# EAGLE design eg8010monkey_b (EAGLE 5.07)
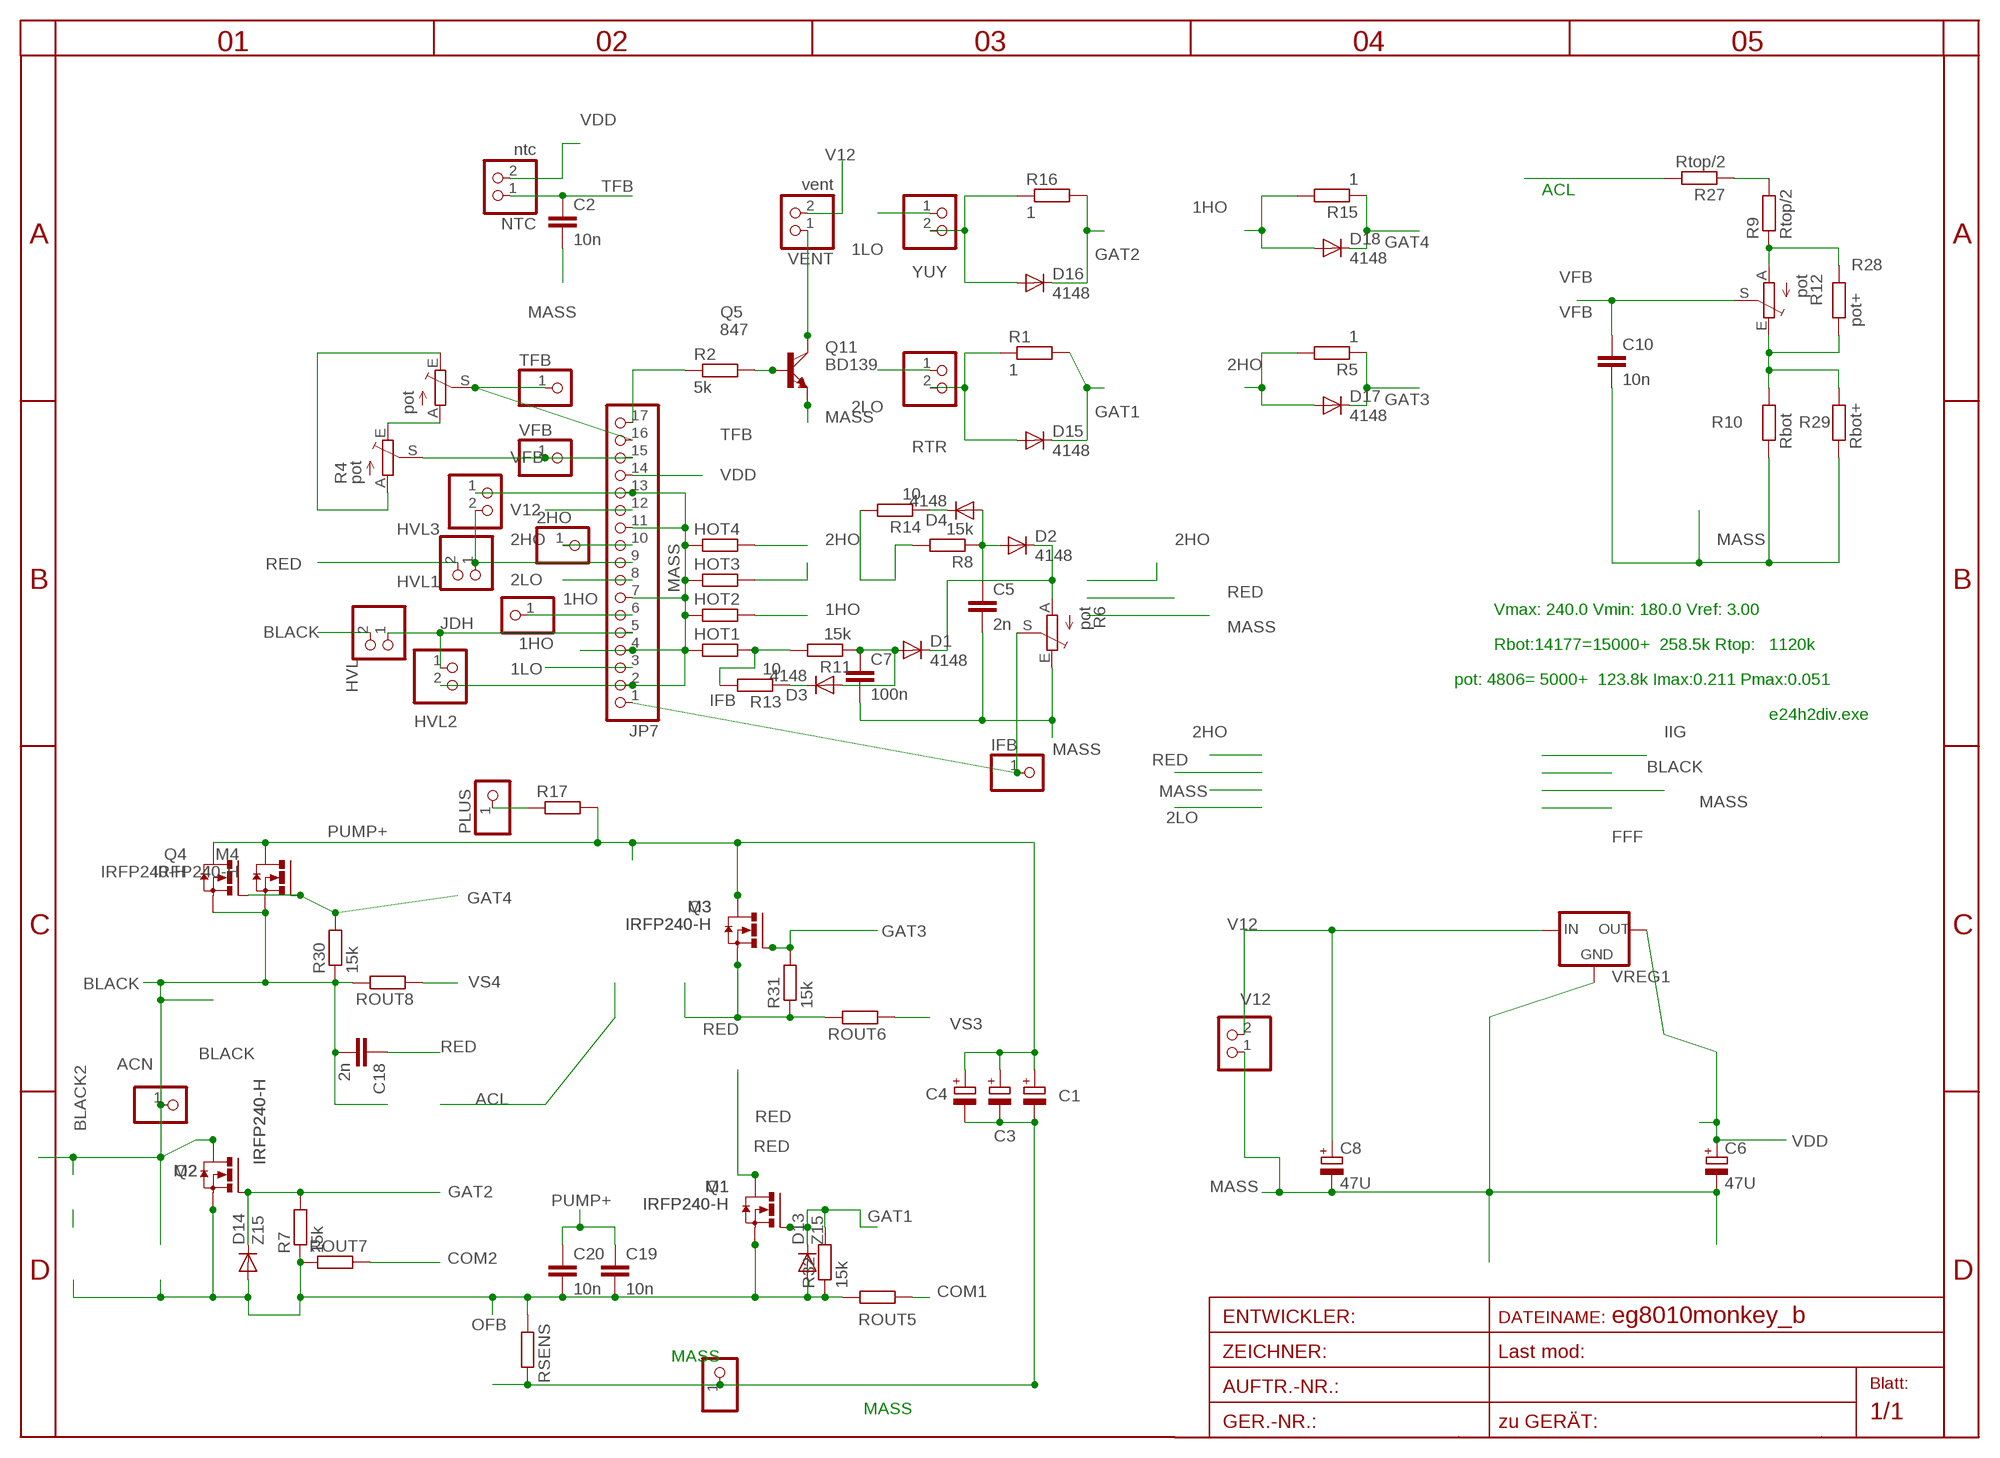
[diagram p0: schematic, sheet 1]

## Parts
1HO  PINHD-1X11MM0  [1X1MM0]
1LO  PINHD-1X2STR  [1X02]
2HO  PINHD-1X11MM0  [1X1MM0]
2LO  PINHD-1X2STR  [1X02]
BLACK2  ACN  PINHD-1X12MM3  [1X2MM3]
C1  CPOL-EUE5-13  [E5-13]
C2  10n  C-EUC0805  [C0805]
C3  CPOL-EUE5-13  [E5-13]
C4  CPOL-EUE5-13  [E5-13]
C5  2n  C-EUC0805  [C0805]
C6  47U  CPOL-EUSMCA  [SMC_A]
C7  100n  C-EUC0805  [C0805]
C8  47U  CPOL-EUSMCA  [SMC_A]
C10  10n  C-EUC0805  [C0805]
C18  2n  C-EU050-024X044  [C050-024X044]
C19  10n  C-EU050-024X044  [C050-024X044]
C20  10n  C-EU050-024X044  [C050-024X044]
D1  4148  DIODE-MINIMELF  [MINIMELF]
D2  4148  DIODE-MINIMELF  [MINIMELF]
D3  4148  DIODE-MINIMELF  [MINIMELF]
D4  4148  DIODE-MINIMELF  [MINIMELF]
D13  Z15  DIODE-MINIMELF  [MINIMELF]
D14  Z15  DIODE-MINIMELF  [MINIMELF]
D15  4148  DIODE-MINIMELF  [MINIMELF]
D16  4148  DIODE-MINIMELF  [MINIMELF]
D17  4148  DIODE-MINIMELF  [MINIMELF]
D18  4148  DIODE-MINIMELF  [MINIMELF]
HOT1  R-EU_R0805  [R0805]
HOT2  R-EU_R0805  [R0805]
HOT3  R-EU_R0805  [R0805]
HOT4  R-EU_R0805  [R0805]
HVL  PINHD-1X2STR  [1X02]
HVL1  PINHD-1X2STR  [1X02]
HVL2  PINHD-1X2STR  [1X02]
HVL3  PINHD-1X2STR  [1X02]
IFB  PINHD-1X11MM0  [1X1MM0]
JP7  PINHD-1X17  [1X17]
M1  IRFP240-H  [TO247BH]
M2  IRFP240-H  [TO247BH]
M3  IRFP240-H  [TO247BH]
M4  IRFP240-H  [TO247BH]
MINUS  PINHD-1X12MM3  [1X2MM3]
NTC  ntc  PINHD-1X2STR  [1X02]
PLUS  PINHD-1X12MM3  [1X2MM3]
Q1  IRFP240-H  [TO247BH]
Q2  IRFP240-H  [TO247BH]
Q3  IRFP240-H  [TO247BH]
Q4  IRFP240-H  [TO247BH]
Q5  847  BC847SMD  [SOT23]
Q11  BD139  [TO126AV]
R1  1  R-EU_R2512  [R2512]
R2  5k  R-EU_R0805  [R0805]
R3  pot  TRIM_EU-RAND160  [RANDL]
R4  pot  TRIM_EU-RAND160  [RANDL]
R5  1  R-EU_R2512  [R2512]
R6  pot  TRIM_EU-RAND160  [RANDL]
R7  15k  R-EU_R1206  [R1206]
R8  15k  R-EU_R0805  [R0805]
R9  Rtop/2  R-EU_R1206  [R1206]
R10  Rbot  R-EU_R0805  [R0805]
R11  15k  R-EU_R0805  [R0805]
R12  pot  TRIM_EU-B64Y  [B64Y]
R13  10  R-EU_R0805  [R0805]
R14  10  R-EU_R0805  [R0805]
R15  1  R-EU_R2512  [R2512]
R16  1  R-EU_R2512  [R2512]
R17  R-EU_0309/10  [0309/10]
R27  Rtop/2  R-EU_R1206  [R1206]
R28  pot+  R-EU_R0805  [R0805]
R29  Rbot+  R-EU_R0805  [R0805]
R30  15k  R-EU_R1206  [R1206]
R31  15k  R-EU_R1206  [R1206]
R32  15k  R-EU_R1206  [R1206]
ROUT5  R-EU_R2512  [R2512]
ROUT6  R-EU_R2512  [R2512]
ROUT7  R-EU_R2512  [R2512]
ROUT8  R-EU_R2512  [R2512]
RSENS  R-EU_WIRE  [WIRE]
TFB  PINHD-1X11MM0  [1X1MM0]
V12  PINHD-1X2STR  [1X02]
VENT  vent  PINHD-1X2STR  [1X02]
VFB  PINHD-1X11MM0  [1X1MM0]
VREG1  LP2950TO92-2MIL  [TO92-2MIL]

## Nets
1HO: 1HO.1 D18.A HOT2.2 JP7.6 R8.2 R14.2 R15.2
1LO: 1LO.1 HOT1.2 JP7.3 R11.2 R13.2
2HO: 2HO.1 D17.A HOT4.2 JP7.10 R5.2
2LO: 2LO.1 HOT3.2 JP7.8
ACL: R27.2
BLACK: BLACK2.1 C18.2 HVL.2 M2.D M4.S Q2.D Q4.S R30.1 ROUT8.2
COM1: ROUT5.1
COM2: ROUT7.2
DFG: HVL1.1 HVL3.2 JP7.9
GAT1: D13.C D15.C M1.G Q1.G R1.2 R32.2
GAT2: D14.C D16.C M2.G Q2.G R7.2 R16.2
GAT3: D17.C M3.G Q3.G R5.1 R31.2
GAT4: D18.C M4.G Q4.G R15.1 R30.2
IFB: IFB.1 JP7.1 R6.S
JDH: HVL2.1 HVL.1 JP7.5
MASS: C1.- C2.2 C3.- C4.- C5.2 C6.- C7.2 C8.- C10.2 HOT1.1 HOT2.1 HOT3.1 HOT4.1 HVL2.2 HVL3.1 JP7.2 JP7.4 JP7.7 JP7.11 JP7.13 MINUS.1 Q5.2(E) Q11.E R3.A R4.E R6.E R10.1 R29.1 RSENS.2 V12.1 VREG1.2(GND)
N$1: Q5.3(C) Q11.C VENT.1
N$2: Q5.1(B) Q11.B R2.2
N$3: JP7.17 R2.1
N$4: D1.C D2.C R6.A
N$5: PLUS.1 R17.1
N$6: C5.1 D2.A D4.A R8.1
N$7: C7.1 D1.A D3.A R11.1
N$8: D3.C R13.1
N$11: D4.C R14.1
N$23: R9.2 R27.1
N$29: R10.2 R12.E R28.1 R29.2
N$30: R9.1 R12.A R28.2
OFB: C19.2 C20.2 D13.A D14.A M1.S M2.S Q1.S Q2.S R7.1 R32.1 ROUT5.2 ROUT7.1 RSENS.1
PUMP+: C1.+ C3.+ C4.+ C19.1 C20.1 M3.D M4.D Q3.D Q4.D R17.2
RED: C18.1 HVL1.2 M1.D M3.S Q1.D Q3.S R31.1 ROUT6.2
RTR: 2LO.2 D15.A R1.1
TFB: C2.1 JP7.16 NTC.1 R3.S TFB.1
V12: C8.+ JP7.12 V12.2 VENT.2 VREG1.3(IN)
VDD: C6.+ JP7.14 NTC.2 R3.E R4.A VREG1.1(OUT)
VFB: C10.1 JP7.15 R4.S R12.S VFB.1
VS3: ROUT6.1
VS4: ROUT8.1
YUY: 1LO.2 D16.A R16.1

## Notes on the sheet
- Vmax: 240.0 Vmin: 180.0 Vref: 3.00
- Rbot:14177=15000+  258.5k Rtop:   1120k
- pot: 4806= 5000+  123.8k Imax:0.211 Pmax:0.051
- e24h2div.exe

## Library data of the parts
1HO 2HO BLACK2 IFB MINUS PLUS TFB VFB = pinhead:PINHD-1X1: PIN HEADER
1LO 2LO HVL HVL1-HVL3 NTC V12 VENT = pinhead:PINHD-1X2: PIN HEADER
C1 C3 C4 C6 C8 = rcl:CPOL-EU: POLARIZED CAPACITOR, European symbol
C2 C5 C7 C10 C18-C20 = rcl:C-EU: CAPACITOR, European symbol
D1-D4 D13-D18 = diode:DIODE-: DIODE
HOT1-HOT4 R1 R2 R5 R7 R8 R11 R13-R17 R30-R32 ROUT5-ROUT8 RSENS = rcl:R-EU_: RESISTOR, European symbol
JP7 = pinhead:PINHD-1X17: PIN HEADER
M1-M4 Q1-Q4 = transistor-power:IRFP240: HEXFET Power MosFet Source: http://www.irf.com/
Q5 = transistor-npn:BC847*: NPN Transistor
Q11 = transistor-power:BD139: NPN TRANSISTOR
R3 R4 R6 R12 = pot:TRIM_EU-: POTENTIOMETER
R9 R10 R27-R29 = rcl-2:R-EU_: RESISTOR, European symbol
VREG1 = v-reg:LP2950?*: Source: http://cache.national.com/ds/LP/LP2950.pdf

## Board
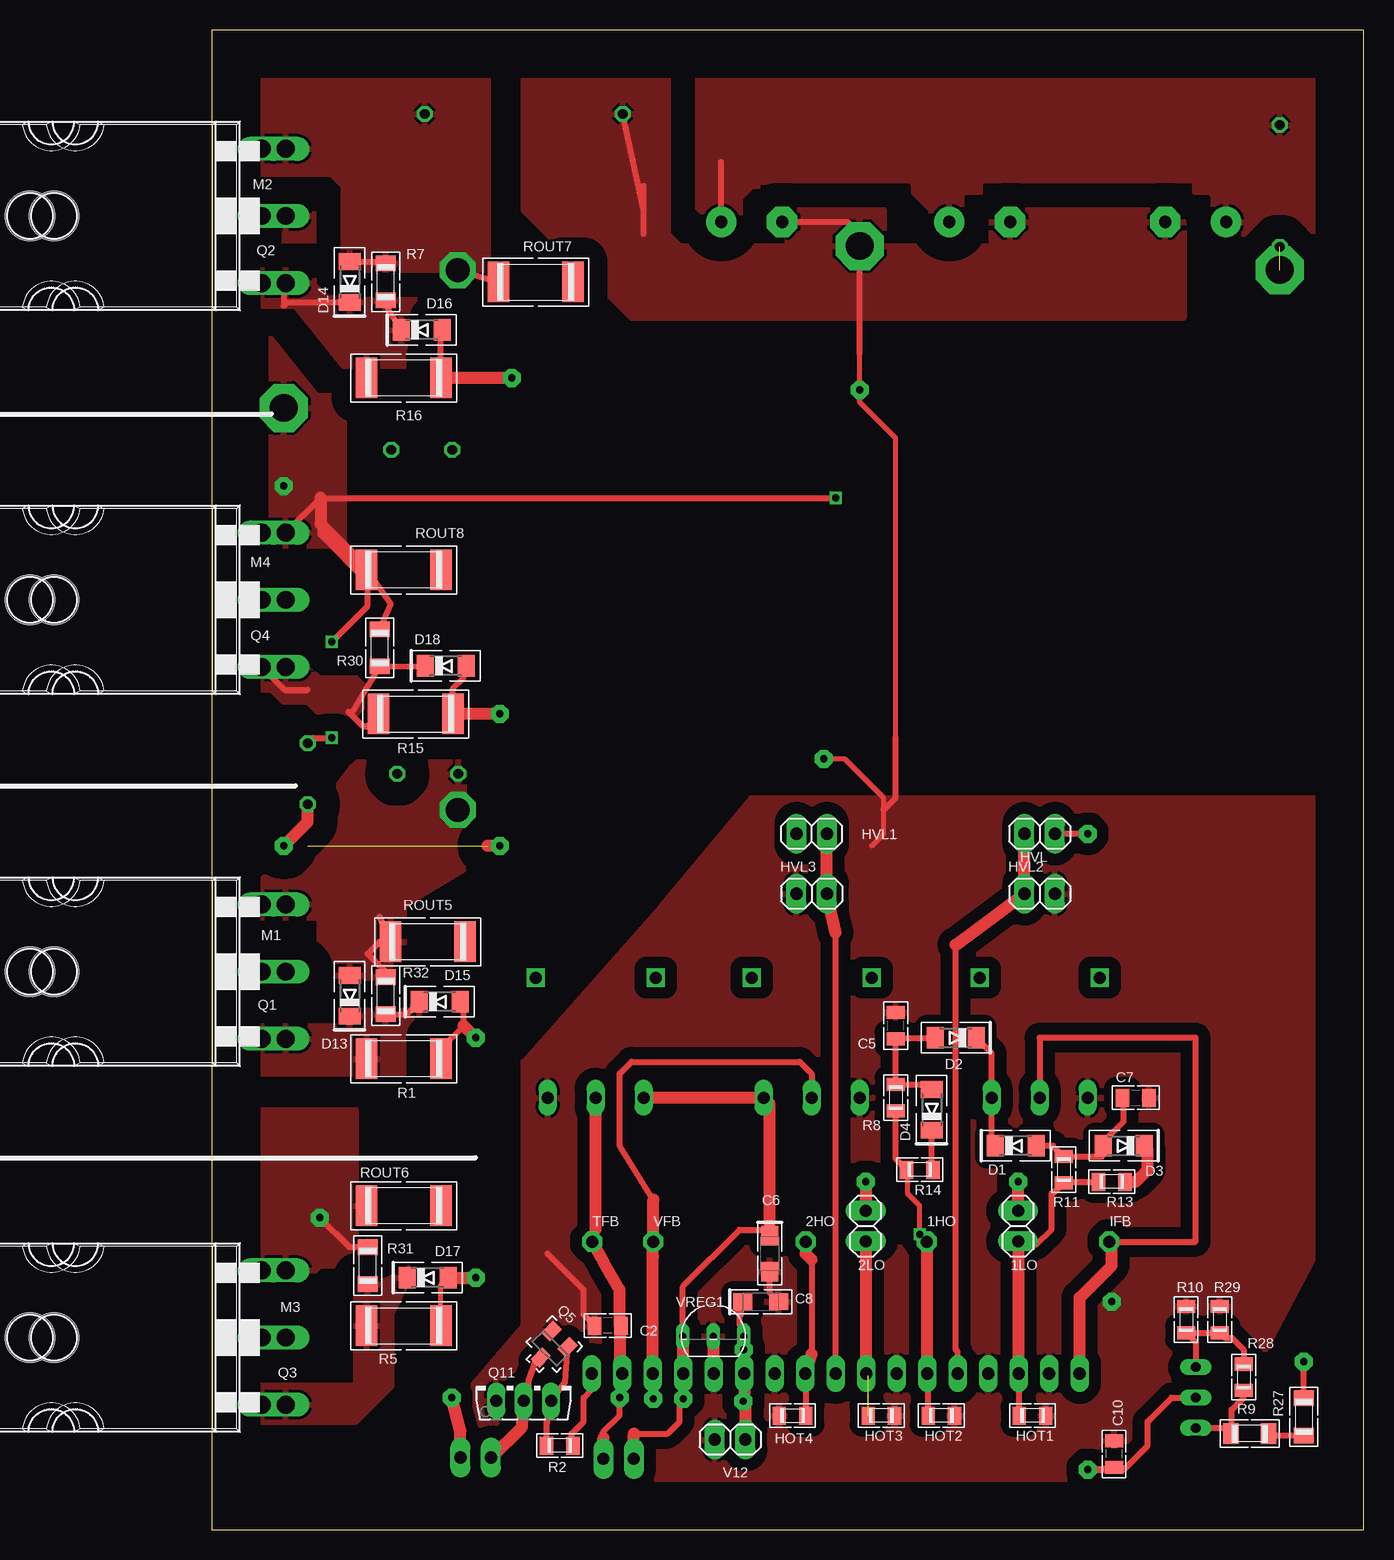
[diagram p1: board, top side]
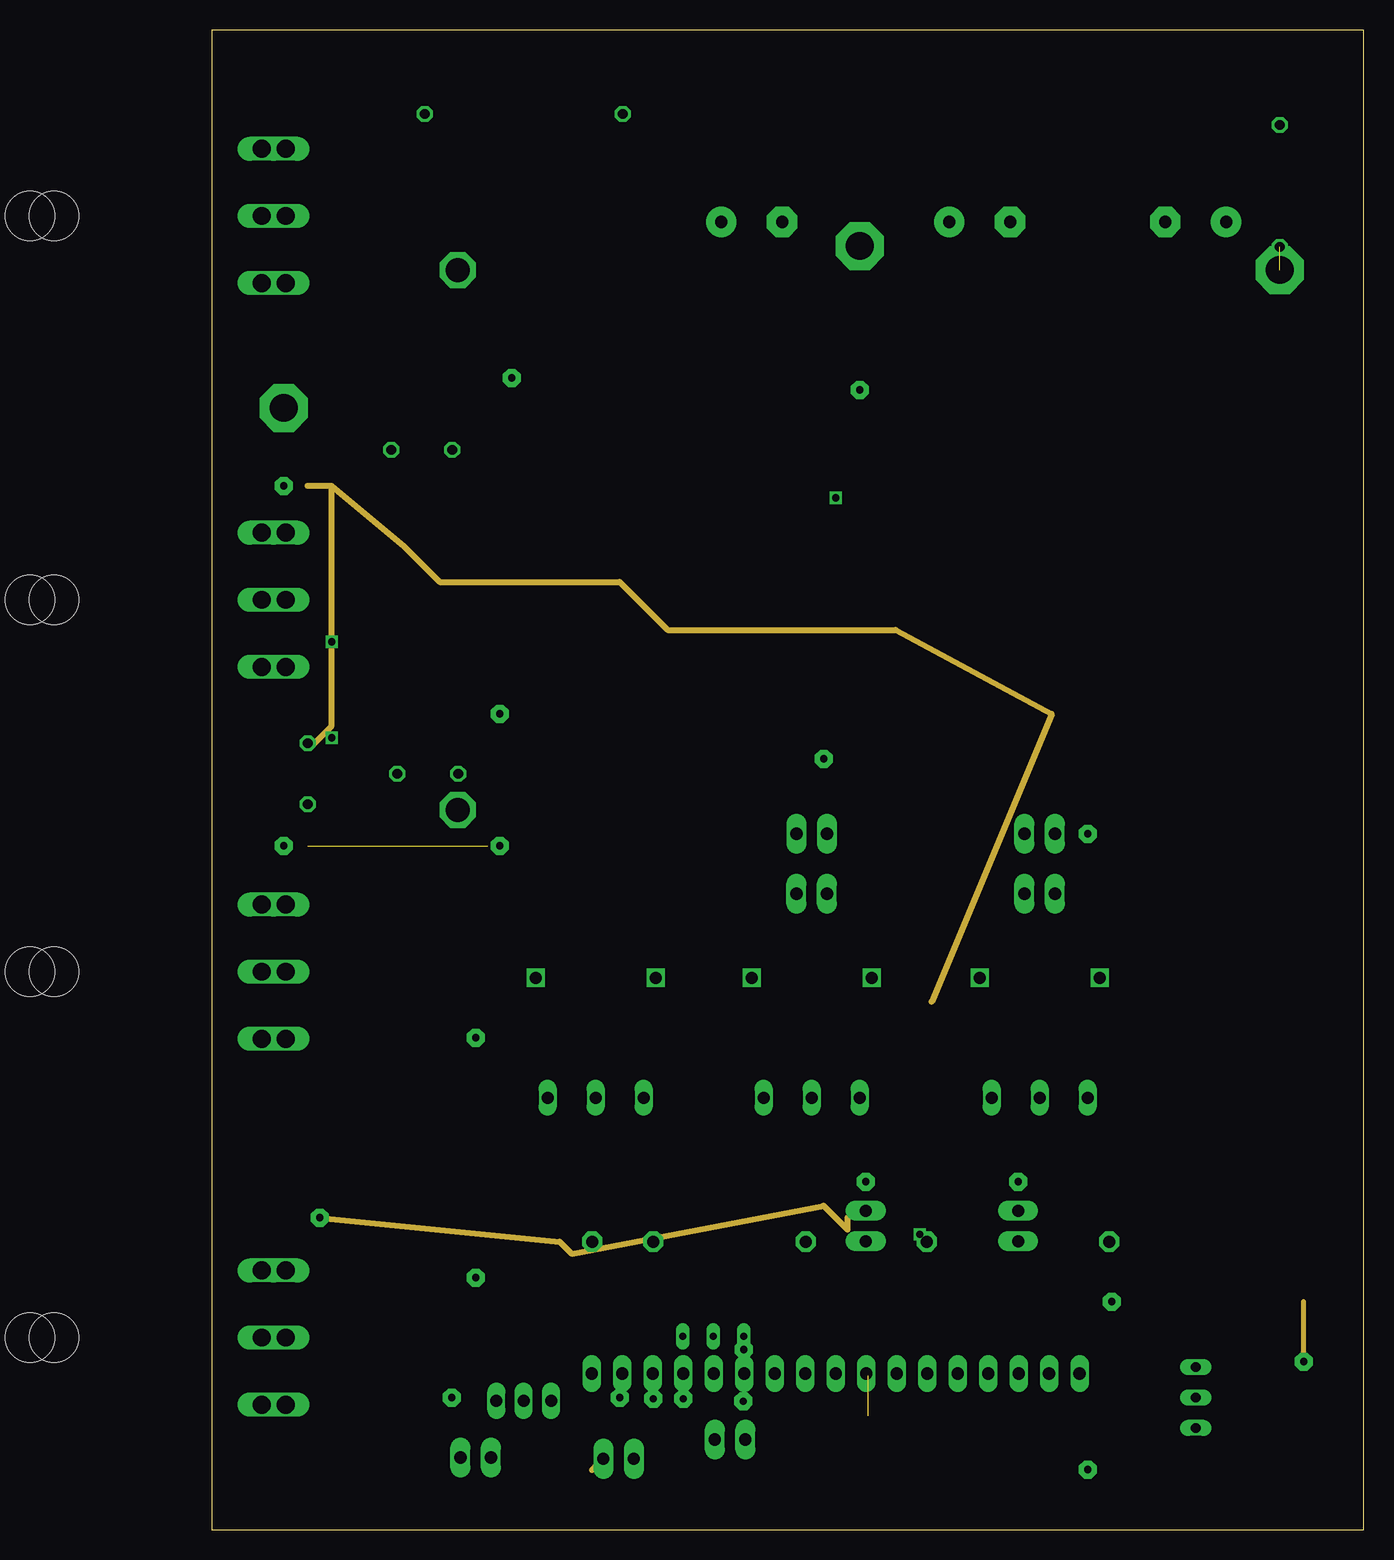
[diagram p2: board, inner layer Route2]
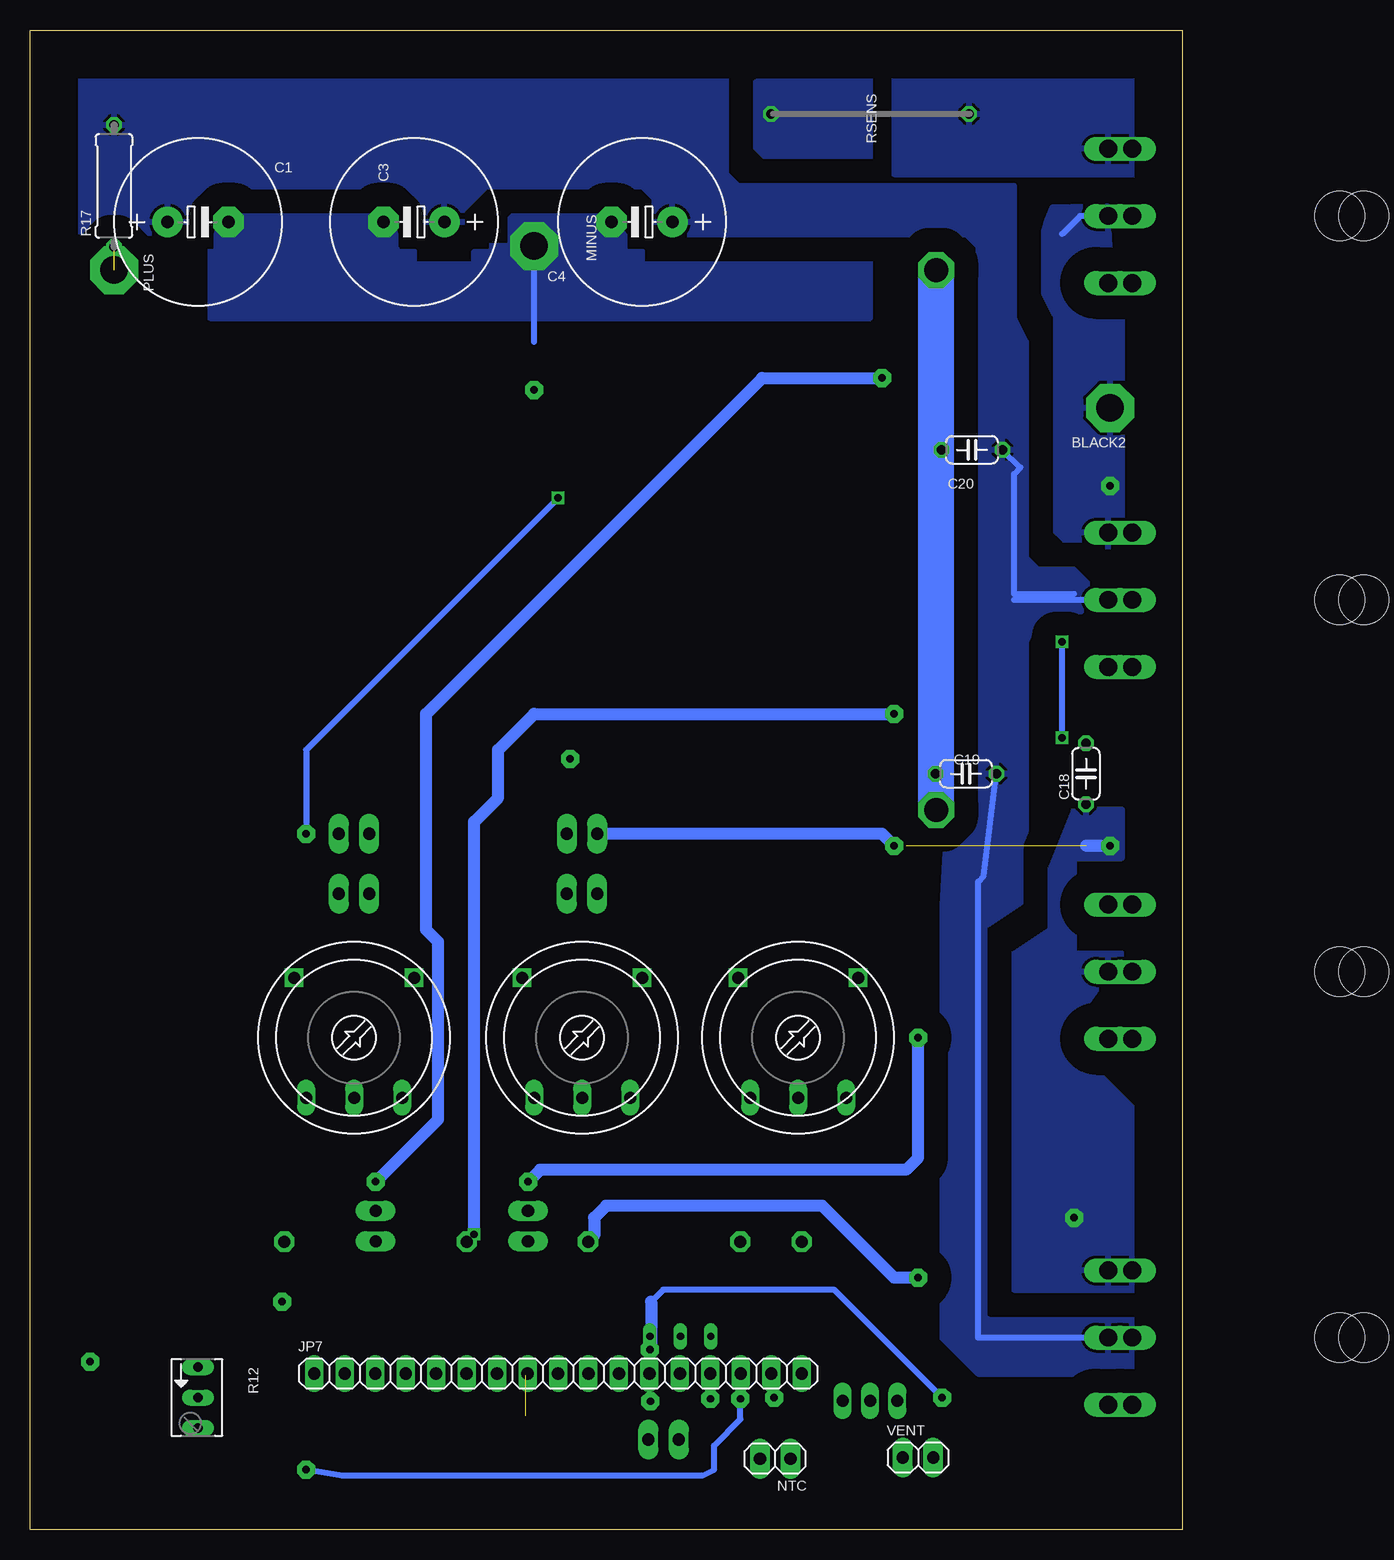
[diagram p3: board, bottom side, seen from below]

Size 96 x 125 mm. Coordinates in mm from the lower left corner, seen from the top.
Outline: 0,0 96,0 96,125 0,125 0,0
Copper layers (1*16): Top 0.035mm / dielectric 1.5mm / Bottom 0.035mm
Design rules "default *": minimum track width 10mil, minimum drill 20mil, track to track 8mil, track to pad 8mil, pad to pad 8mil, via to via 8mil, smd to smd 8mil, copper to edge 4mm, drill to drill 8mil, minimum pad ring 10mil, minimum via ring 8mil, stop-mask expansion 4mil, vias tented up to drill 0mil, thermal gap 10mil

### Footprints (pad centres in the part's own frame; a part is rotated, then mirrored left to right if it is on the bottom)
1X1MM0 = drill 1 pad 1.676 octagon: 1 0,0
1X02 = drill 1.016 pad 1.676 long: 1 -1.27,0; 2 1.27,0
1X2MM3 = drill 2.3 pad 4 octagon: 1 0,0
E5-13 = drill 1.016 pad 2.54 round: + -2.54,0 | drill 1.016 pad 2.54 octagon: - 2.54,0
C0805 = smd 1.1 x 1.5: 1 -1.1,0; 2 1.1,0
SMC_A = smd 1.6 x 1.4: + -1.5,0; - 1.5,0
C050-024X044 = drill 0.813 octagon: 1 -2.54,0; 2 2.54,0
MINIMELF = smd 1.4 x 1.8: A 1.7,0; C -1.7,0
R0805 = smd 1.1 x 1.5: 1 -1.1,0; 2 1.1,0
1X17 = drill 1.016 long: 1 -20.32,0; 2 -17.78,0; 3 -15.24,0; 4 -12.7,0; 5 -10.16,0; 6 -7.62,0; 7 -5.08,0; 8 -2.54,0; 9 0,0; 10 2.54,0; 11 5.08,0; 12 7.62,0; 13 10.16,0; 14 12.7,0; 15 15.24,0; 16 17.78,0; 17 20.32,0
TO247BH = drill 1.499 long: D 0,-10.16; G -5.588,-10.16; S 5.588,-10.16 | hole 4.115: 0,9.144
SOT23 = smd 1 x 1.4: 1 -0.95,-1.1; 2 0.95,-1.1; 3 0,1.1
TO126AV = drill 1 pad 1.27 long: B 2.286,-1.27; C 0,-1.27; E -2.286,-1.27
R2512 = smd 1.8 x 3.4: 1 -3.1,0; 2 3.1,0
RANDL = drill 1 long: A -4,5; E 4,5; S 0,5 | drill 1 square: P$1 -5,-5; P$2 5,-5
R1206 = smd 1.3 x 1.7: 1 -1.55,0; 2 1.55,0
B64Y = drill 0.813 long: A 2.54,0; E -2.54,0; S 0,0
0309/10 = drill 0.813 octagon: 1 -5.08,0; 2 5.08,0
WIRE = drill 0.813 octagon: 1 -8.25,0; 2 8.25,0
TO92-2MIL = drill 0.6 pad 0.813 long: 1 -2.54,0; 2 0,0; 3 2.54,0

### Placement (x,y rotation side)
1HO  59.6,24 0 top
1LO  67.2,25.3 90 top
2HO  49.5,24 0 top
2LO  54.5,25.3 90 top
BLACK2  6,93.5 180 bottom
C1  82,109 0 bottom
C2  33,17 180 top
C3  64,109 180 bottom
C4  45,109 180 bottom
C5  57,42 90 top
C6  46.5,23 270 top
C7  77,36 0 top
C8  45.75,19 0 top
C10  75.2,6.3 90 top
C18  8,63 90 bottom
C19  18,63 180 bottom
C20  17.5,90 180 bottom
D1  67,32 0 top
D2  62,41 180 top
D3  76,32 180 top
D4  60,35 90 top
D13  11.5,44.5 90 top
D14  11.5,104 90 top
D15  19,44 0 top
D16  17.5,100 0 top
D17  18,21 0 top
D18  19.5,72 0 top
HOT1  68.4,9.5 180 top
HOT2  60.8,9.5 180 top
HOT3  55.8,9.5 180 top
HOT4  48.4,9.5 0 top
HVL  69,58 0 top
HVL1  50,58 180 top
HVL2  69,53 0 top
HVL3  50,53 0 top
IFB  74.8,24 0 top
JP7  52,13 0 bottom
M1  -4,46.5 90 top
M2  -4,109.5 90 top
M3  -4,16 90 top
M4  -4,77.5 90 top
MINUS  54,107 270 bottom
NTC  33.9,5.9 180 bottom
PLUS  89,105 270 bottom
Q1  -6,46.5 90 top
Q2  -6,109.5 90 top
Q3  -6,16 90 top
Q4  -6,77.5 90 top
Q5  28.2,15.1 135 top
Q11  26,12 0 top
R1  16,39.25 180 top
R2  29,7 180 top
R3  32,41 180 bottom
R4  50,41 180 bottom
R5  16,17 0 top
R6  69,41 180 bottom
R7  14.5,104 270 top
R8  57,36 270 top
R9  86.5,8 0 top
R10  81.2,17.5 270 top
R11  71,30 270 top
R12  82,11 270 bottom
R13  75,29 180 top
R14  59,30 180 top
R15  17,68 0 top
R16  16,96 180 top
R17  89,112 90 bottom
R27  91,9.4 90 top
R28  86,12.7 270 top
R29  84,17.5 270 top
R30  14,73.5 270 top
R31  13,22 270 top
R32  14.5,44.5 270 top
ROUT5  18,49 180 top
ROUT6  16,27 180 top
ROUT7  27,104 0 top
ROUT8  16,80 180 top
RSENS  26,118 180 bottom
TFB  31.7,24 0 top
V12  43.2,7.5 0 top
VENT  22,6 0 bottom
VFB  36.8,24 0 top
VREG1  41.8,16.1 0 top

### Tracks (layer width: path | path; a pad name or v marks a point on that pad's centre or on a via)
1HO  (via drill 0.6, 0.6 pad 1.5)
  Top 0.406: v59,24.6 59,27 58,28 58,29.9 R14.2
  Top 0.5: HOT2.2 59.7,12.92 JP7.6 | 59.62,23.62 1HO.1 | R8.2 57,30.9 R14.2 | R15.2 20.1,70.1 21,71 21,71.8 D18.A
  Top 1: JP7.6 59.62,23.62 | v24,68 R15.2
  Bottom 1: v24,68 54,68 57,65 57,61 59,59 v59,24.6 1HO.1
1LO
  Top 0.5: HOT1.2 67.3,12.94 JP7.3 | 67.24,23.49 1LO.1 68.73,23.73 70,25 70,28 70.1,28 R11.2 71.1,29 R13.2
  Top 1: JP7.3 67.24,23.49
2HO  (via drill 0.6 pad 1.5)
  Top 0.406: R5.2 19.1,20.4 D17.A
  Top 0.5: HOT4.2 49.5,12.96 JP7.10 | 50,22.5 50,14.64
  Top 1: 50,14.64 JP7.10 | 50,22.5 49.5,23 2HO.1 | D17.A v22,21
  Bottom 1: v22,21 24,21 30,27 48,27 49,26 49,24.5 2HO.1
2LO  (1 unrouted)
  Top 0.5: JP7.8 54.7,12.84 | 54.54,23.27 2LO.1
  Top 1: JP7.8 54.54,23.27
ACL  (via drill 0.6 pad 1.5)
  Top 0.5: R27.2 v91,14
  Route2 0.406: v91,14 91,19
BLACK  (via drill 0.6, 0.6 pad 1.5)
  Top 0.5: Q4.S M4.S 9.07,86 | ROUT8.2 14.9,77.15 R30.1 | v73,58 HVL.2 | 9.07,86 v52,86 | 9.07,86 9.07,82.93 13,79 13,77 v10,74 | v10,66 8.46,66 C18.2
  Top 1: 9.07,86 9.07,83.83 ROUT8.2
  Route2 0.5: C18.2 8.54,65.54 10,67 v10,74 10,87 | 60,44 70,68 57,75 38,75 34,79 19,79 16,82 10,87 | 10,87 8,87
  Bottom 0.5: M2.D 8.5,109.5 10,108 | v73,58 73,65 v52,86 | v10,66 v10,74
  other vias: 6,87
  pour Bottom (isolate 2, rank 3): 6.2,110.3 10.8,110.2 arc-41 11.4,100.5 11,100 11,82 6,82 6,83 5,84 5,105 6,106
  pour Top (isolate 2, rank 3): 6.2,110.3 10.8,110.2 arc-41 11.4,100.5 11,100 11,82 6,82 6,83 5,84 5,105 6,106
DFG
  Top 0.5: JP7.9 52,49.73
  Top 1: 52,49.73 HVL3.2 HVL1.1
GAT1
  Top 0.5: R32.2 16.25,42.95 D15.C
  pour Top (isolate 2): 3,42 11,42 11,44 18,44 16,38 3,38
GAT2
  Top 0.5: R7.2 14.85,101.45 D16.C | D14.C 6.3,102.3 6,102 6,104 6.07,104 M2.G
  pour Top (isolate 2, rank 2): 2,105 8,105 15,103 18,103 18,97 11,97 7,102 2,102
GAT3
  pour Top (isolate 2, rank 3): 3,12 3,9 12,9 15,12 15,18 17,22 12,20 12,12
GAT4
  Top 0.5: Q4.G 6.07,70 8,70 | 11.62,67.95 R30.2 14.75,71.95 D18.C | 11.62,67.95 11.39,68.18 | R15.1 12.9,66.9 13,67 12.57,67 11.62,67.95
  pour Top (isolate 1.5): 2.9,72.5 6.9,72.5 9,71 12,71 13,70 13,69 12,68 9,68 8,69 6,69 5,70 3,70
IFB
  Top 0.5: IFB.1 82,24 82,41 69,41 R6.S
  Top 1: JP7.1 72.32,19.32 75,22 75,23.8 IFB.1
JDH
  Top 0.5: JP7.5 62.16,14.84 62,15 62,48.73
  Top 1: 62,48.73 HVL2.1 HVL.1
MASS  (via drill 0.6 pad 1.5)
  Top 0.406: 54,98 v54,95 54,94 57,91 57,66 | 51.25,64 v51,64.25 52.75,64.25 56,61 56,60 56,58 55,57
  Top 0.5: 36,110 36,112 | 47,109 C4.- 53,109 54,108 54,98 | 36,108 36,110 | 36,110 RSENS.2 | 41.84,16.06 VREG1.2 | C6.- 46.5,19.75 C8.- | 28,23 31,20 31,17.9 C2.2 | 57,66 57,61 56,60
  Top 1: JP7.13 41.84,16.06
  Bottom 0.5: 54,99 MINUS.1
  other vias: 75,19
  pour Top (isolate 1, rank 4): 45,61 92,61 92,23 82,4 20,4 20,10 26,17 26,39 37.5,52
  pour Bottom (isolate 2, rank 3, no thermals): 26,101 26,121 35,121 38,119 38,108 39,107 45.8,107 48,110 56,110 56,107 65,107 65,110 80,110 81,109 81,101
  pour Top (isolate 2, rank 2): 26,121 38,121 38,108 39,107 48,107 48,110 56,110 56,107 65,107 65,110 80,110 81,109 81,101 35,101 26,110
N$1
  Top 0.5: Q5.3 27.02,14.02 26.4,12.4 26.4,11.13 Q11.C 25.9,10.63 25.9,9.4
  Top 1: VENT.1 25.87,8.57 25.9,9.4
N$2
  Top 0.5: Q5.1 29.45,12.29 Q11.B | Q11.B 28.02,10 | R2.2 27.9,8.9 28,9 28,10.44 Q11.B
N$3
  Top 0.5: JP7.17 31.68,11.68 31,11 31,9 30,8 30,7.1 R2.1
N$4
  Top 0.5: D2.C 65,39.7 R6.A 65,32.3 D1.C
N$5  (1 unrouted)
N$6
  Top 0.5: D2.A 57.1,41 C5.1 R8.1 59.6,37.1 D4.A
N$7
  Top 0.5: D1.A 70.1,32 R11.1 74.2,31.1 D3.A 74.3,32.3 76,34 76,34.9 C7.1
N$8
  Top 1: R13.1 77,29 78,30 78,31.7 D3.C
N$11
  Top 0.5: D4.C 60,30.1 R14.1
N$23
  Top 0.5: R27.1 88.2,7.85 R9.2
N$29
  Top 0.5: R28.1 86,15 85,16 84.4,16 R29.2 R10.2 82,15.6 R12.E
N$30
  Top 0.5: R12.A 84.49,8.46 R9.1 85,8.05 85,10 86,11 R28.2
OFB  (via drill 2 pad 1.5)
  Top 0.5: D14.A 14.35,105.7 R7.1 | 14,51.1 ROUT5.2 14,49 13,48 14.5,46.5 R32.1 | v20.5,105 ROUT7.1
  Bottom 0.5: v20.5,105 20.5,90.46 C20.2
  Bottom 3: v20.5,60 v20.5,105
  pour Top (isolate 2, rank 2): 3,51 3,54 4,54 6,56 12,64 21,64 21,55 16,52 16,46 9,46 9,51
  pour Top: 3,121 23,121 23,105 12,105 11,106 11,112 10,113 4,113 3,114
  pour Bottom (rank 4): 3,121 24,121 24,113 4,113 3,114
PUMP+
  Top 0.5: C4.+ 42.46,114 | Q4.D M4.D
  Bottom 0.5: 14,78 14,88 13.46,88.54 C20.1 | 14,78 9,78 | 11,77.5 14,77.5 | M4.D 11,77.5 | 11,77.5 14,78 | M3.D 17,16 17,54 16.54,54.46 C19.1
  pour Bottom (isolate 2, rank 2): 38,121 92,121 92,108 83,108 79,112 66,112 63,109 63,108 60,108 60,110 58,112 45,112 44,111 44,108 18,108 17,107 17,84 13,84 13,99 14,101 14,112 37,112 38,113
  pour Top (isolate 2, rank 4): 40,121 92,121 92,108 83,108 79,112 66,112 63,109 63,108 60,108 60,110 58,112 45,112 44,111 44,108 17,108 16,107 11,109 14,112 37,112 38,113
  pour Bottom (isolate 2, rank 2): 3,18 13,18 13,74 12,76 9,76 7,78 9,80 12,80 13,81 13,90 14,91 15,91 18,88 20,52 20,16 17,13 4,13 3,14
RED  (via drill 0.6 pad 1.5)  (1 unrouted)
  Top 0.5: R31.1 11.45,23.55 v9,26 | Q1.D M1.D
  Top 1: C18.1 8,59 v6,57 | v24,57 23,57
  Route2 0.5: v9,26 29,24 30,23 51,27 53,25 53,26
  Bottom 1: HVL1.2 25,58 v24,57 | v6,57 8,57
  pour Top (isolate 2): 4,21 4,35 12,35 12,24 13,24 11,22 9,22 8,21
  pour Bottom (isolate 2): 5,60 9,60 11,55 11,50 14,48 14,20 4,20 4,35 10,41 5,48 9,48 9,56 5,56
RTR  (via drill 0.6 pad 1.5)
  Top 0.5: R1.1 19.1,40.1 21,42 21,43.7 D15.A | v54.5,29 54.5,29.5
  Top 1: v54.5,29 2LO.2 | v22,41 21,42
  Bottom 1: v22,41 22,31 23,30 53.5,30 v54.5,29
TFB  (via drill 0.6 pad 1.5)
  Top 0.5: 34,13.22 JP7.16 34,12.78 v34,11 34,9.5 32.6,8.1 32.63,7.63 | TFB.1 32,25 | C2.1 34,17.1
  Top 1: 34,13.22 C2.1 | NTC.1 32.63,7.63 | 32,25 R3.S | TFB.1 32.7,22.2 34,20 34,17.1
  Route2 0.5: 31.68,4.95 NTC.1
V12  (via drill 0.6 pad 1.5)
  Top 0.5: JP7.12 44.2,13.18 | 44.34,13.04 JP7.12 | 44,18 43.8,18.2 | 44,18 44,17.1 44.3,16.8 44.3,16.14 VREG1.3 | C8.+ 44.1,17.9 44,18 | JP7.12 44.47,12.91 | 44.47,10.53 v44.3,10.7 44.38,10.78
  Top 1: 44.34,13.04 v44.34,15 VREG1.3 | VENT.2 20.73,8.27 v20,11 | 44.47,10.53 V12.2 | JP7.12 44.38,10.78
  Bottom 0.5: v20,11 29,20 43.25,20 C8.+ | VREG1.3 44.25,16.19 | 44.25,15.09 v44.34,15 | v44.3,10.7 44.3,11.2
  Bottom 1: C8.+ 44.25,15.09
VDD  (via drill 0.6 pad 1.5)
  Top 0.5: 39.3,16.06 VREG1.1 39.26,20.26 44,25 46,25 C6.+ | JP7.14 v39.3,10.9 39,10.6 39,9 38,8 35.2,8 | 46.5,35.5 R4.A
  Top 1: JP7.14 39.3,16.06 | R4.A R3.E | C6.+ 46.5,35.5 | NTC.2 35.17,7.97 35.2,8
  Bottom 0.5: v39.3,10.9 39.4,10.6
VFB  (via drill 0.6 pad 1.5)
  Top 0.5: 36.8,27.5 34,32 34,38 35,39 49,39 50,38 R4.S | JP7.15 36.76,10.94 v36.8,10.9 | R12.S 80,11 78,9 78,7 76,5 v73,5 C10.1
  Top 1: JP7.15 36.76,22.76 VFB.1 36.8,27.5
  Bottom 0.5: v36.8,10.9 36.8,9.2 39,7 39,5 40,4.5 70,4.5 v73,5
YUY  (via drill 0.6 pad 1.5)
  Top 0.5: D16.A 19.1,100 R16.1
  Top 1: 1LO.2 v67.2,29 | v25,96 R16.1
  Bottom 1: v25,96 35,96 63,68 63,50 62,49 62,34.2 v67.2,29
